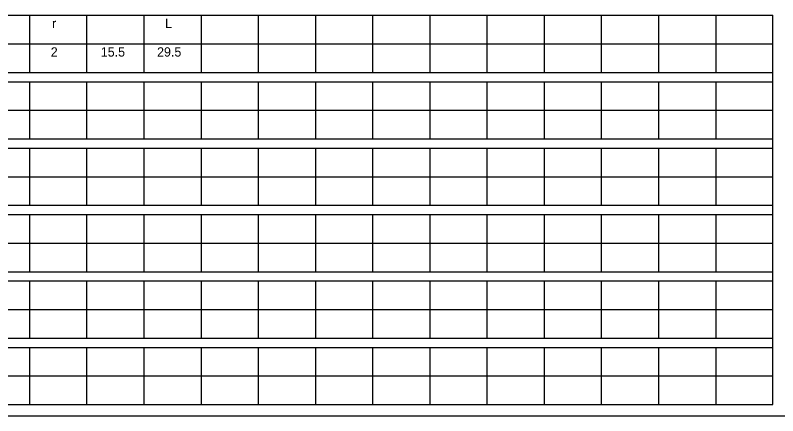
# Model space of a CAD drawing. Extents: x -875 to -645, y -2221 to -2162.
# Drawn here: x -774.22 to -766.2, y -2211.08 to -2206.87 of the extents above; entities that cross this region are included whole.
import ezdxf

# ---------------------------------------------------------------- set-up
doc = ezdxf.new("R2010")
doc.units = 0
doc.layers.add('GSSign', color=7, linetype='Continuous')
doc.layers.add('SheetLinesMisc2_dp', color=7, linetype='Continuous')

msp = doc.modelspace()

# ---------------------------------------------------------------- linework, layer by layer
at = {"layer": 'SheetLinesMisc2_dp'}
for p, q in [((-781.0439, -2206.8664), (-766.2466, -2206.8664)), ((-774.0719, -2206.8664), (-774.0719, -2207.4676)), ((-773.47, -2206.8664), (-773.47, -2207.4676)), ((-772.868, -2206.8664), (-772.868, -2207.4676)), ((-772.2661, -2206.8664), (-772.2661, -2207.4676)), ((-771.664, -2206.8664), (-771.664, -2207.4676)), ((-771.0622, -2206.8664), (-771.0622, -2207.4676)), ((-770.4603, -2206.8664), (-770.4603, -2207.4676)), ((-769.8584, -2206.8664), (-769.8584, -2207.4676)), ((-769.2563, -2206.8664), (-769.2563, -2207.4676)), ((-768.6544, -2206.8664), (-768.6544, -2207.4676)), ((-768.0525, -2206.8664), (-768.0525, -2207.4676)), ((-767.4506, -2206.8664), (-767.4506, -2207.4676)), ((-766.8485, -2206.8664), (-766.8485, -2207.4676)), ((-766.2466, -2210.9634), (-766.2466, -2206.8664)), ((-781.0439, -2207.167), (-766.2466, -2207.167)), ((-781.0439, -2207.4676), (-766.2466, -2207.4676)), ((-781.0439, -2207.5657), (-766.2466, -2207.5657)), ((-774.0719, -2207.5657), (-774.0719, -2208.1667)), ((-773.47, -2207.5657), (-773.47, -2208.1667)), ((-772.868, -2207.5657), (-772.868, -2208.1667)), ((-772.2661, -2207.5657), (-772.2661, -2208.1667)), ((-771.664, -2207.5657), (-771.664, -2208.1667)), ((-771.0622, -2207.5657), (-771.0622, -2208.1667)), ((-770.4603, -2207.5657), (-770.4603, -2208.1667)), ((-769.8584, -2207.5657), (-769.8584, -2208.1667)), ((-769.2563, -2207.5657), (-769.2563, -2208.1667)), ((-768.6544, -2207.5657), (-768.6544, -2208.1667)), ((-768.0525, -2207.5657), (-768.0525, -2208.1667)), ((-767.4506, -2207.5657), (-767.4506, -2208.1667)), ((-766.8485, -2207.5657), (-766.8485, -2208.1667)), ((-781.0439, -2207.8663), (-766.2466, -2207.8662)), ((-781.0439, -2208.1667), (-766.2466, -2208.1667)), ((-781.0439, -2208.2648), (-766.2466, -2208.2648)), ((-774.0719, -2208.2648), (-774.0719, -2208.8659)), ((-773.47, -2208.2648), (-773.47, -2208.8659)), ((-772.868, -2208.2648), (-772.868, -2208.8659)), ((-772.2661, -2208.2648), (-772.2661, -2208.8659)), ((-771.664, -2208.2648), (-771.664, -2208.8659)), ((-771.0622, -2208.2648), (-771.0622, -2208.8659)), ((-770.4603, -2208.2648), (-770.4603, -2208.8659)), ((-769.8584, -2208.2648), (-769.8584, -2208.8659)), ((-769.2563, -2208.2648), (-769.2563, -2208.8659)), ((-768.6544, -2208.2648), (-768.6544, -2208.8659)), ((-768.0525, -2208.2648), (-768.0525, -2208.8659)), ((-767.4506, -2208.2648), (-767.4506, -2208.8659)), ((-766.8485, -2208.2648), (-766.8485, -2208.8659)), ((-781.0439, -2208.5654), (-766.2466, -2208.5654)), ((-781.0439, -2208.8659), (-766.2466, -2208.8659)), ((-781.0439, -2208.9639), (-766.2466, -2208.9639)), ((-774.0719, -2208.9639), (-774.0719, -2209.5652)), ((-773.47, -2208.9639), (-773.47, -2209.5652)), ((-772.868, -2208.9639), (-772.868, -2209.5652)), ((-772.2661, -2208.9639), (-772.2661, -2209.5652)), ((-771.664, -2208.9639), (-771.664, -2209.5652)), ((-771.0622, -2208.9639), (-771.0622, -2209.5652)), ((-770.4603, -2208.9639), (-770.4603, -2209.5652)), ((-769.8584, -2208.9639), (-769.8584, -2209.5652)), ((-769.2563, -2208.9639), (-769.2563, -2209.5652)), ((-768.6544, -2208.9639), (-768.6544, -2209.5652)), ((-768.0525, -2208.9639), (-768.0525, -2209.5652)), ((-767.4506, -2208.9639), (-767.4506, -2209.5652)), ((-766.8485, -2208.9639), (-766.8485, -2209.5652)), ((-781.0439, -2209.2646), (-766.2466, -2209.2646)), ((-781.0439, -2209.5652), (-766.2466, -2209.5652)), ((-781.0439, -2209.6632), (-766.2466, -2209.6632)), ((-774.0719, -2209.6632), (-774.0719, -2210.2643)), ((-773.47, -2209.6632), (-773.47, -2210.2643)), ((-772.868, -2209.6632), (-772.868, -2210.2643)), ((-772.2661, -2209.6632), (-772.2661, -2210.2643)), ((-771.664, -2209.6632), (-771.664, -2210.2643)), ((-771.0622, -2209.6632), (-771.0622, -2210.2643)), ((-770.4603, -2209.6632), (-770.4603, -2210.2643)), ((-769.8584, -2209.6632), (-769.8584, -2210.2643)), ((-769.2563, -2209.6632), (-769.2563, -2210.2643)), ((-768.6544, -2209.6632), (-768.6544, -2210.2643)), ((-768.0525, -2209.6632), (-768.0525, -2210.2643)), ((-767.4506, -2209.6632), (-767.4506, -2210.2643)), ((-766.8485, -2209.6632), (-766.8485, -2210.2643)), ((-781.0439, -2209.9637), (-766.2466, -2209.9637)), ((-781.0439, -2210.2643), (-766.2466, -2210.2643)), ((-781.0439, -2210.3624), (-766.2466, -2210.3624)), ((-774.0719, -2210.3624), (-774.0719, -2210.9634)), ((-773.47, -2210.3624), (-773.47, -2210.9634)), ((-772.868, -2210.3624), (-772.868, -2210.9634)), ((-772.2661, -2210.3624), (-772.2661, -2210.9634)), ((-771.664, -2210.3624), (-771.664, -2210.9634)), ((-771.0622, -2210.3624), (-771.0622, -2210.9634)), ((-770.4603, -2210.3624), (-770.4603, -2210.9634)), ((-769.8584, -2210.3624), (-769.8584, -2210.9634)), ((-769.2563, -2210.3624), (-769.2563, -2210.9634)), ((-768.6544, -2210.3624), (-768.6544, -2210.9634)), ((-768.0525, -2210.3624), (-768.0525, -2210.9634)), ((-767.4506, -2210.3624), (-767.4506, -2210.9634)), ((-766.8485, -2210.3624), (-766.8485, -2210.9634)), ((-781.0439, -2210.6628), (-766.2466, -2210.6628)), ((-781.0439, -2210.9634), (-766.2466, -2210.9634)), ((-781.1882, -2211.0815), (-751.1006, -2211.0815))]:
    msp.add_line(p, q, dxfattribs=at)

# ---------------------------------------------------------------- texts
at = {"layer": 'GSSign'}
for s, height, p in [('r', 0.098, (-773.8349, -2207.001)), ('L', 0.098, (-772.645, -2207.001)), ('2', 0.098, (-773.8475, -2207.3016)), ('15.5', 0.09803, (-773.3213, -2207.3016)), ('29.5', 0.09803, (-772.7286, -2207.3016))]:
    msp.add_text(s, height=height, dxfattribs=at).set_placement(p)

doc.saveas('drawing.dxf')
